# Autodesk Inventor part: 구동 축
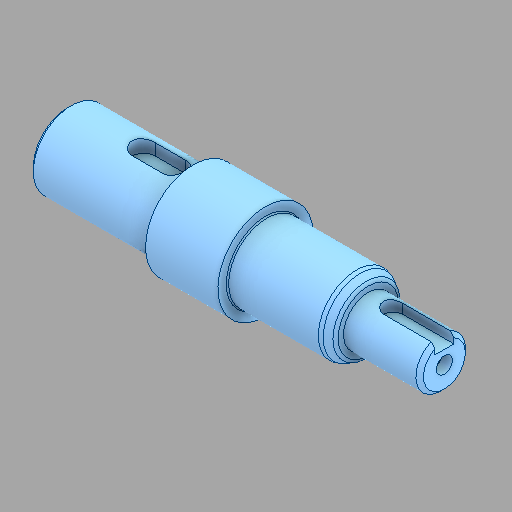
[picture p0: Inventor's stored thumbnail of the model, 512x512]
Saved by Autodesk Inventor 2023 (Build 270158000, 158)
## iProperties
Created: 2025-09
Part Number: 구동 축
Material: 강철, 탄소
Document SubType Name: Modeling
Designer: home
Density: 7.85 g/cm^3
Appearance: 기본값
Author: jhkim
Sending System: Autodesk Inventor 2026
Preprocessor: ST-DEVELOPER v20.1
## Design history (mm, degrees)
feature "솔리드1"
node "솔리드2"
